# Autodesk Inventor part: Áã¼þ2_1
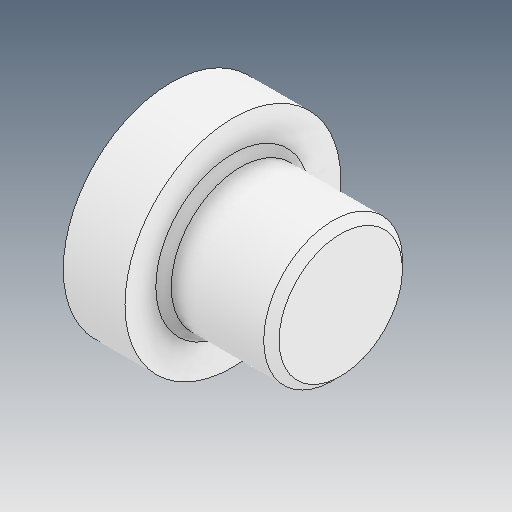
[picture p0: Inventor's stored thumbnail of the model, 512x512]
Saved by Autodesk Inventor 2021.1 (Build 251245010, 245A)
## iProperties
Created: 2021-05
Part Number: Áã¼þ2_1
Material: Ogólny
Document SubType Name: Modeling
Designer: user
Density: 1 g/cm^3
Appearance: Domyślna
Author: user
Revision Number: ÈÎºÎ
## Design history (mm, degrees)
feature "ÊäÈë1"
node "Bryła1"
